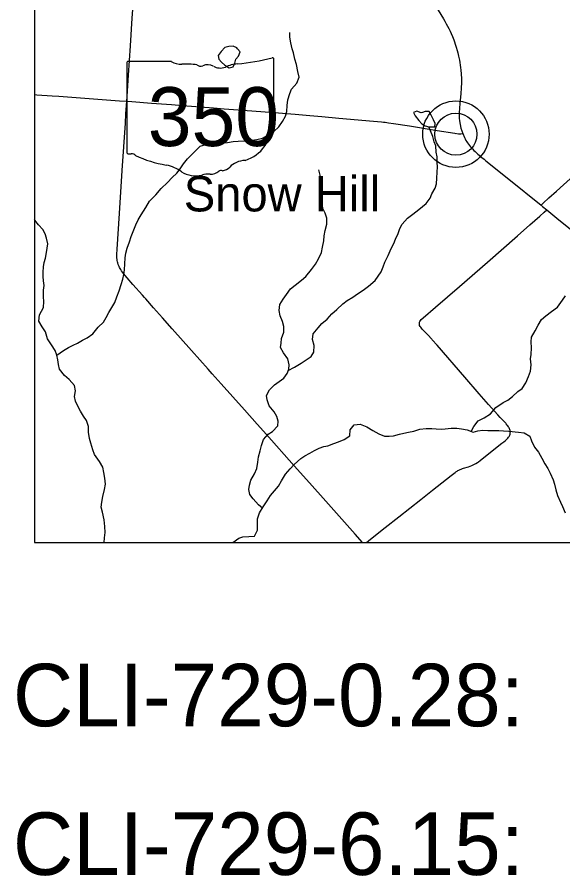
# Model space of a CAD drawing. Extents: x 0 to 34, y 0 to 22.
# Drawn here: x 24.749 to 25.971, y 13.559 to 15.483 of the extents above; entities that cross this region are included whole.
import ezdxf

# ---------------------------------------------------------------- set-up
doc = ezdxf.new("R2010")
doc.units = 0
for name, color, linetype in [('GM_X_Corporation', 7, 'Continuous'), ('GM_X_Major_River', 7, 'Continuous'), ('GM_X_Minor_Lake', 7, 'Continuous'), ('GM_X_Minor_River', 7, 'Continuous'), ('GM_X_State_Location', 7, 'Continuous'), ('GM_X_State_Route', 7, 'Continuous'), ('GM_X_State_Shield', 7, 'Continuous'), ('GM_X_Township_Road', 7, 'Continuous'), ('GM_X_Unincorporated', 7, 'Continuous'), ('GM_X_Unincorporated_Location', 7, 'Continuous'), ('GM_X_Unincorporated_Text', 7, 'Continuous'), ('SH_Text', 7, 'Continuous')]:
    doc.layers.add(name, color=color, linetype=linetype)

msp = doc.modelspace()

# ---------------------------------------------------------------- linework, layer by layer
at = {"layer": 'GM_X_Corporation'}
for points in [[(31.5875, 16.2767), (31.5875, 21.1059), (24.7875, 21.1059), (24.7875, 14.3059), (28.9316, 14.3059), (29.0116, 14.3654), (30.2271, 15.2782), (30.4064, 15.4161), (30.5426, 15.5161)], [(24.7875, 21.0754), (24.7875, 14.3059), (28.9316, 14.3059), (29.0116, 14.3654), (30.2271, 15.2782), (30.4064, 15.4161), (30.2965, 15.5727), (29.7308, 16.376), (29.4482, 16.7745), (28.3618, 18.3058), (27.7955, 19.0474), (27.3085, 19.7612), (27.122, 19.8586), (26.9873, 19.9283), (26.0175, 20.4289), (25.0178, 20.9472)]]:
    msp.add_lwpolyline(points, close=True, dxfattribs=at)
at = {"layer": 'GM_X_Major_River'}
for points in [[(25.232, 14.3059), (25.2452, 14.3156), (25.2548, 14.3189), (25.268, 14.3194), (25.2806, 14.32), (25.2876, 14.3336), (25.2874, 14.3476), (25.2875, 14.3586), (25.2919, 14.3722), (25.3, 14.3858), (25.3089, 14.3993), (25.3167, 14.4114), (25.3251, 14.4215), (25.334, 14.432), (25.3414, 14.4437), (25.3499, 14.4587), (25.3603, 14.4708), (25.3695, 14.4805), (25.3841, 14.494), (25.3937, 14.4999), (25.4044, 14.5062), (25.4147, 14.5118), (25.4258, 14.5169), (25.4357, 14.5206), (25.4452, 14.5228), (25.4581, 14.5275), (25.4688, 14.5316), (25.4818, 14.5367), (25.494, 14.5449), (25.4949, 14.5582), (25.5038, 14.5698), (25.5175, 14.5708), (25.5322, 14.5653), (25.5457, 14.5571), (25.5589, 14.549), (25.5721, 14.5439), (25.5823, 14.5441), (25.5918, 14.5451), (25.6051, 14.5488), (25.6154, 14.5505), (25.6253, 14.5527), (25.6374, 14.5552), (25.6508, 14.5596), (25.6652, 14.5613), (25.6781, 14.5615), (25.6879, 14.5602), (25.6985, 14.5597), (25.708, 14.5607), (25.7213, 14.5621), (25.7338, 14.5619), (25.744, 14.5602), (25.7573, 14.5586), (25.7705, 14.5527), (25.7807, 14.5564), (25.7925, 14.5573), (25.8031, 14.5568), (25.8145, 14.5571), (25.8278, 14.5569), (25.8384, 14.5564), (25.8505, 14.5551)], [(25.8505, 14.5551), (25.8717, 14.5533), (25.8849, 14.5512), (25.8973, 14.5442), (25.9014, 14.5339), (25.908, 14.5198), (25.9166, 14.5083), (25.924, 14.4949), (25.931, 14.482), (25.9377, 14.472), (25.9432, 14.4613), (25.9495, 14.4464), (25.9524, 14.4369), (25.9556, 14.424), (25.9596, 14.411), (25.9659, 14.3965), (25.9703, 14.3866), (25.9765, 14.3721)]]:
    msp.add_lwpolyline(points, dxfattribs=at)
at = {"layer": 'GM_X_Minor_Lake'}
for points in [[(25.2427, 15.412), (25.2409, 15.4142), (25.2326, 15.4173), (25.2231, 15.4166), (25.214, 15.4144), (25.2056, 15.4058), (25.1994, 15.3967), (25.2005, 15.3884), (25.2065, 15.3818), (25.2144, 15.3753)], [(25.2144, 15.3753), (25.2238, 15.3692), (25.2326, 15.3714), (25.2368, 15.3797), (25.2384, 15.3884), (25.2445, 15.3955), (25.2484, 15.4046), (25.2427, 15.412)], [(25.6571, 15.2691), (25.6543, 15.2681), (25.6445, 15.2724), (25.6365, 15.269), (25.6406, 15.2614), (25.6488, 15.2515), (25.6556, 15.2438), (25.6632, 15.2392), (25.6715, 15.2372)], [(25.6715, 15.2372), (25.6844, 15.2371), (25.6856, 15.2447), (25.6819, 15.2527), (25.6767, 15.263), (25.6718, 15.2714), (25.6627, 15.2711), (25.6571, 15.2691)]]:
    msp.add_lwpolyline(points, dxfattribs=at)
at = {"layer": 'GM_X_Minor_River'}
for points in [[(24.8378, 14.7257), (24.853, 14.736), (24.8637, 14.7424), (24.874, 14.748), (24.8839, 14.7525), (24.8954, 14.7588), (24.9053, 14.7644), (24.9183, 14.7734), (24.9305, 14.7881), (24.942, 14.7997), (24.9486, 14.8099), (24.9544, 14.8209), (24.9613, 14.8322), (24.9678, 14.8432), (24.9725, 14.8564), (24.9772, 14.8693), (24.9819, 14.884), (24.9858, 14.8961), (24.9878, 14.9064), (24.9894, 14.917), (24.9903, 14.9299), (24.9911, 14.9432), (24.9924, 14.9538), (24.9951, 14.9651), (25.0006, 14.9795), (25.0041, 14.9912), (25.0084, 15.0026), (25.015, 15.0177), (25.02, 15.029), (25.0265, 15.0396), (25.0373, 15.0562), (25.0454, 15.0706), (25.0592, 15.0849), (25.0715, 15.0988), (25.0856, 15.112), (25.096, 15.1236), (25.1063, 15.1334), (25.1144, 15.1432), (25.1213, 15.1538), (25.1305, 15.1654), (25.1447, 15.1794), (25.1585, 15.1933), (25.1741, 15.1981), (25.1847, 15.1983), (25.1984, 15.2001), (25.2101, 15.2012), (25.2204, 15.2022), (25.2326, 15.204), (25.2439, 15.2046), (25.2587, 15.2053), (25.2701, 15.2067), (25.2857, 15.2084), (25.2983, 15.2114), (25.3108, 15.2181), (25.3242, 15.2267), (25.3349, 15.2368), (25.3434, 15.2489), (25.3499, 15.261), (25.3527, 15.2712), (25.354, 15.2849), (25.3556, 15.2974), (25.3595, 15.3114), (25.3638, 15.3216), (25.3757, 15.3348), (25.3803, 15.348), (25.3778, 15.3606), (25.3749, 15.3765), (25.3712, 15.3887), (25.3683, 15.4024), (25.3646, 15.4119), (25.3617, 15.4252), (25.3595, 15.4378), (25.36, 15.4484)], [(25.3563, 14.6913), (25.3702, 14.6983), (25.3851, 14.7073), (25.3966, 14.7148), (25.4073, 14.7223), (25.4138, 14.7321), (25.4143, 14.7469), (25.4106, 14.7606), (25.4123, 14.7735), (25.423, 14.787), (25.4318, 14.7968), (25.4433, 14.8058), (25.4541, 14.8183), (25.4651, 14.828), (25.4785, 14.8408), (25.4885, 14.8476), (25.5007, 14.8558), (25.5114, 14.8629), (25.5243, 14.8711), (25.5358, 14.8798), (25.5507, 14.8925), (25.5576, 14.9023), (25.5642, 14.9121), (25.5685, 14.9235), (25.5723, 14.9337), (25.5804, 14.9484), (25.5867, 14.9643), (25.5925, 14.9753), (25.5963, 14.9855), (25.6025, 14.9983), (25.6064, 15.0089), (25.6111, 15.0188), (25.6237, 15.0327), (25.6352, 15.0417), (25.6485, 15.0518), (25.6654, 15.0653), (25.6742, 15.077), (25.6781, 15.0868), (25.685, 15.0993), (25.6882, 15.1091), (25.689, 15.122), (25.6895, 15.1357), (25.6904, 15.1475), (25.6901, 15.1569), (25.6895, 15.1699), (25.6877, 15.1805), (25.6867, 15.1942), (25.6833, 15.2037), (25.6804, 15.2155), (25.6715, 15.2372)], [(25.2983, 14.383), (25.2897, 14.3905), (25.2773, 14.4039), (25.2698, 14.4134), (25.2676, 14.4245), (25.2692, 14.4343), (25.2727, 14.4453), (25.2804, 14.4596), (25.2855, 14.4714), (25.2879, 14.4861), (25.2899, 14.4975), (25.2934, 14.5115), (25.2966, 14.5233), (25.3005, 14.5369), (25.3112, 14.5489), (25.3207, 14.5545), (25.3326, 14.5673), (25.3339, 14.578), (25.3305, 14.5879), (25.3249, 14.5985), (25.3137, 14.6119), (25.3089, 14.6252), (25.3074, 14.6355), (25.314, 14.6476), (25.3251, 14.6593), (25.3358, 14.6664), (25.3461, 14.6743), (25.3538, 14.6844), (25.3573, 14.6943), (25.3582, 14.7041), (25.3552, 14.7171), (25.3459, 14.7308), (25.3388, 14.7426), (25.34, 14.7525), (25.3412, 14.7627), (25.3463, 14.7767), (25.346, 14.79), (25.3431, 14.801), (25.3383, 14.8136), (25.3361, 14.8254), (25.3377, 14.8387), (25.3451, 14.8511), (25.352, 14.8613), (25.3612, 14.8741), (25.3715, 14.882), (25.3861, 14.8933), (25.3956, 14.9019), (25.4083, 14.9174), (25.4175, 14.9294), (25.4241, 14.9411), (25.4306, 14.9555), (25.433, 14.9672), (25.4358, 14.9816), (25.437, 14.9926), (25.4391, 15.0048), (25.4426, 15.0191), (25.4427, 15.0324), (25.4386, 15.0435), (25.4338, 15.0538), (25.432, 15.0671), (25.4322, 15.0811), (25.433, 15.0929), (25.4327, 15.1027), (25.431, 15.1157), (25.4277, 15.1286), (25.4247, 15.1404)], [(24.9434, 14.3059), (24.9448, 14.3162), (24.9457, 14.3287), (24.9454, 14.342), (24.9437, 14.3568), (24.94, 14.3739), (24.9371, 14.385), (24.9384, 14.3963), (24.9404, 14.4092), (24.9443, 14.4247), (24.9467, 14.4365), (24.9449, 14.4502), (24.9427, 14.4627), (24.9406, 14.4745), (24.9335, 14.4875), (24.9222, 14.5031), (24.9182, 14.5134), (24.9137, 14.5283), (24.9112, 14.5389), (24.9083, 14.5534), (24.9084, 14.5655), (24.9043, 14.5792), (24.8976, 14.5891), (24.8909, 14.6002), (24.8853, 14.6097), (24.8797, 14.6227), (24.8775, 14.633), (24.8792, 14.6455), (24.877, 14.6576), (24.8653, 14.6714), (24.8552, 14.6798), (24.8439, 14.694), (24.8417, 14.7046), (24.8403, 14.7149), (24.8378, 14.7259), (24.8341, 14.7362), (24.8255, 14.7488), (24.8168, 14.7622), (24.8121, 14.7778), (24.8046, 14.7888), (24.7975, 14.8014), (24.7991, 14.8155), (24.808, 14.8325), (24.8089, 14.8454), (24.8078, 14.856), (24.808, 14.8712), (24.8092, 14.8814), (24.8078, 14.8917), (24.8071, 14.9019), (24.8072, 14.9118), (24.8081, 14.9236), (24.8093, 14.933), (24.812, 14.9429), (24.8144, 14.9558), (24.8164, 14.9652), (24.8173, 14.9751), (24.8143, 14.9876), (24.8118, 14.9975), (24.8066, 15.0071), (24.7964, 15.0178), (24.7885, 15.0277), (24.7875, 15.0294)], [(25.7659, 14.5547), (25.772, 14.5656), (25.782, 14.5788), (25.7949, 14.5855), (25.8094, 14.5938), (25.821, 14.6081), (25.8378, 14.6197), (25.848, 14.6245), (25.8587, 14.6328), (25.8702, 14.6445), (25.8805, 14.6508), (25.8882, 14.6633), (25.8944, 14.6776), (25.8987, 14.6897), (25.9007, 14.7041), (25.8993, 14.7171), (25.9002, 14.7273), (25.9011, 14.7421), (25.9001, 14.7554), (25.9013, 14.7656), (25.9094, 14.7804), (25.9163, 14.7924), (25.9237, 14.8053), (25.9332, 14.8135), (25.9458, 14.8233), (25.9592, 14.833), (25.9704, 14.8485), (25.9773, 14.8583)]]:
    msp.add_lwpolyline(points, dxfattribs=at)
at = {"layer": 'GM_X_State_Route'}
for points in [[(25.6705, 15.5342), (25.7039, 15.4789), (25.7067, 15.4739), (25.7101, 15.468), (25.7131, 15.4621), (25.7158, 15.457), (25.7186, 15.4512), (25.7213, 15.4458), (25.724, 15.4395), (25.727, 15.4319), (25.7286, 15.427), (25.7303, 15.4219), (25.7323, 15.4151), (25.7343, 15.4081), (25.7358, 15.4025), (25.7376, 15.3954), (25.7396, 15.3863), (25.7404, 15.3812), (25.7414, 15.3752), (25.7421, 15.37), (25.743, 15.3635), (25.7437, 15.3554), (25.7442, 15.3448), (25.7443, 15.3355), (25.7437, 15.3242), (25.7426, 15.3112), (25.7408, 15.2889), (25.7393, 15.2685), (25.7391, 15.2617), (25.7393, 15.2562), (25.7398, 15.2501), (25.741, 15.2425), (25.7429, 15.2343), (25.7471, 15.222)], [(24.7875, 15.3092), (24.7929, 15.3088), (24.827, 15.3064), (24.8425, 15.3054), (24.8716, 15.3033), (24.9007, 15.3008), (24.9782, 15.2954), (24.9944, 15.2942), (25.0055, 15.2934), (25.0501, 15.2902), (25.0947, 15.2869), (25.1195, 15.2851), (25.1888, 15.2794), (25.2123, 15.2774), (25.2743, 15.2725), (25.3245, 15.2689), (25.3715, 15.2652), (25.4048, 15.2623), (25.4222, 15.2608), (25.4314, 15.26), (25.4692, 15.2566), (25.5131, 15.2524), (25.5385, 15.2502), (25.5652, 15.2478), (25.5694, 15.2474), (25.5732, 15.2471), (25.5774, 15.2466), (25.5809, 15.2461), (25.5921, 15.2445), (25.6276, 15.2389), (25.6895, 15.2287), (25.7294, 15.2226), (25.7377, 15.2214), (25.7407, 15.2212), (25.7429, 15.2214), (25.7471, 15.222)], [(25.7471, 15.222), (25.7508, 15.2128), (25.7523, 15.2098), (25.7542, 15.2065), (25.7561, 15.2034), (25.7576, 15.2011), (25.76, 15.1978), (25.7623, 15.1948), (25.7642, 15.1925), (25.7664, 15.1901), (25.7687, 15.1875), (25.7719, 15.1843), (25.7749, 15.1815), (25.7781, 15.1786), (25.7811, 15.1759), (25.7841, 15.1732), (25.7902, 15.1682), (25.795, 15.1642), (25.7989, 15.1609), (25.8502, 15.1196), (25.9225, 15.0612)], [(25.9225, 15.0612), (25.9275, 15.0659), (25.9402, 15.0777), (25.9573, 15.0931), (26.0348, 15.163)], [(25.9225, 15.0612), (25.9256, 15.0588), (25.9356, 15.0507)], [(25.9356, 15.0507), (25.958, 15.0326), (26.0115, 14.9892), (26.0644, 14.9468), (26.1136, 14.9069), (26.1325, 14.8917), (26.1686, 14.8623), (26.1818, 14.8519), (26.22, 14.821), (26.2442, 14.8015), (26.2521, 14.795), (26.258, 14.7903), (26.2636, 14.7856), (26.2698, 14.7802), (26.2798, 14.7717)]]:
    msp.add_lwpolyline(points, dxfattribs=at)
at = {"layer": 'GM_X_State_Shield'}
for p, q in [((25.3241, 15.2836), (25.3241, 15.3883)), ((24.9945, 15.3799), (24.9945, 15.1798)), ((25.0943, 15.3834), (24.9977, 15.3834)), ((25.324, 15.2837), (25.3241, 15.2836))]:
    msp.add_line(p, q, dxfattribs=at)
for centre, major_axis, start_param, end_param in [((25.2067, 15.6562), (0.3495, 0), 4.814394, 5.042369), ((25.3204, 15.3888), (0.00367, 0), 6.141152, 7.989035), ((24.9983, 15.3804), (0.00382, 0), 1.712693, 3.28349), ((25.1172, 15.4066), (0.037, 0), 4.042523, 4.731795), ((25.1295, 15.271), (0.133, 0), 1.404758, 1.657858), ((25.1597, 15.3814), (0.0107, 0), 3.836095, 5.185415), ((25.1754, 15.3583), (0.0222, 0), 0.950623, 2.079405), ((25.2041, 15.39), (0.0267, 0), 4.081561, 5.145723), ((25.2513, 15.3223), (0.0703, 0), 1.699011, 2.107814), ((25.3232, 15.276), (0.00568, 0), 1.883978, 3.671073), ((25.2871, 15.2627), (0.0341, 0), 5.934695, 6.695948), ((25.3202, 15.2832), (0.00393, 0), 5.05454, 6.418171), ((25.3372, 15.2398), (0.0248, 0), 2.387724, 3.262537), ((25.2263, 15.2265), (0.0874, 0), 5.101752, 6.440018), ((24.9983, 15.1794), (0.00385, 0), 3.00124, 4.508301), ((24.9989, 15.1998), (0.0294, 0), 4.665946, 4.897461), ((25.0049, 15.1683), (0.0106, 0), 0.519207, 1.627899), ((25.1387, 15.3481), (0.2524, 0), 4.195997, 4.488961), ((25.2631, 15.1236), (0.0479, 0), 1.647645, 2.488434), ((25.0635, 15.0899), (0.079, 0), 0.823519, 1.323587), ((25.1489, 15.1673), (0.0501, 0), 4.026481, 4.996735), ((25.1815, 15.1523), (0.0267, 0), 4.691044, 5.507374), ((25.2057, 15.1329), (0.00752, 0), 1.147584, 2.315152), ((25.2025, 15.1604), (0.0282, 0), 4.937069, 5.64225), ((25.1778, 15.0981), (0.0412, 0), 1.495662, 1.94098)]:
    msp.add_ellipse(centre, major_axis=major_axis, ratio=0.8, start_param=start_param, end_param=end_param, dxfattribs=at)
at = {"layer": 'GM_X_Township_Road'}
for points in [[(24.9944, 15.2942), (24.9951, 15.3048), (24.998, 15.3526), (25.0026, 15.4182), (25.0067, 15.4802), (25.0097, 15.5198)], [(25.5229, 14.3059), (25.5062, 14.3243), (25.488, 14.3447), (25.4703, 14.3647), (25.4403, 14.3987), (25.4039, 14.4395), (25.3696, 14.478), (25.3072, 14.548), (25.2869, 14.5707), (25.2585, 14.6028), (25.2062, 14.6611), (25.186, 14.6839), (25.1765, 14.6945), (25.1391, 14.7361), (25.0962, 14.7844), (25.0741, 14.8088), (25.0545, 14.8313), (25.0368, 14.8517), (25.0341, 14.8548), (25.0293, 14.8601), (25.008, 14.8839), (24.9954, 14.8985), (24.987, 14.9085), (24.9848, 14.9116), (24.9827, 14.9145), (24.981, 14.9172), (24.9797, 14.9193), (24.9783, 14.9219), (24.9771, 14.9243), (24.9754, 14.9283), (24.9741, 14.9324), (24.9735, 14.9347), (24.9729, 14.9372), (24.9726, 14.9401), (24.9722, 14.9434), (24.9722, 14.9479), (24.9722, 14.9508), (24.973, 14.9626), (24.9783, 15.0432), (24.9844, 15.1393), (24.9879, 15.192), (24.9913, 15.2453), (24.9926, 15.2664), (24.9944, 15.2942)], [(25.5314, 14.3059), (25.5366, 14.3101), (25.5736, 14.3395), (25.6043, 14.3638), (25.653, 14.4024), (25.6794, 14.4231), (25.7002, 14.4398), (25.7213, 14.4562), (25.7302, 14.463), (25.7319, 14.4641), (25.7343, 14.4658), (25.7364, 14.4669), (25.7386, 14.4682), (25.7411, 14.4693), (25.7437, 14.4705), (25.7463, 14.4715), (25.7489, 14.4725), (25.7603, 14.4757), (25.7636, 14.4769), (25.7673, 14.4782), (25.7703, 14.4796), (25.7735, 14.4811), (25.7762, 14.4828), (25.7799, 14.485), (25.7824, 14.4869), (25.7858, 14.4894), (25.8095, 14.5086), (25.8349, 14.5285), (25.8389, 14.5316), (25.8419, 14.5339), (25.8452, 14.5367), (25.8468, 14.5383), (25.8483, 14.5397), (25.8496, 14.5416), (25.8509, 14.5433), (25.8518, 14.5448), (25.8525, 14.5466), (25.8531, 14.5483), (25.8536, 14.5507), (25.8537, 14.5522), (25.8538, 14.5538), (25.8536, 14.5557), (25.8534, 14.5568), (25.8528, 14.5592), (25.8521, 14.5608), (25.8513, 14.5626), (25.8505, 14.5638), (25.8497, 14.5652), (25.8483, 14.5671), (25.847, 14.5688), (25.8447, 14.5714), (25.8433, 14.5729), (25.8309, 14.5861), (25.8255, 14.5921), (25.8048, 14.6152), (25.7838, 14.639), (25.7515, 14.6759), (25.6895, 14.7479), (25.6788, 14.7601), (25.6776, 14.7615), (25.6692, 14.7707), (25.6563, 14.7841), (25.653, 14.7879), (25.6516, 14.7899), (25.6506, 14.7922), (25.6502, 14.794), (25.65, 14.7958), (25.6501, 14.7977), (25.6505, 14.7995), (25.6512, 14.8012), (25.6525, 14.8033), (25.6541, 14.8052), (25.6582, 14.809), (25.6861, 14.8329), (25.7395, 14.8795), (25.8023, 14.9341), (25.8697, 14.993), (25.8973, 15.0171), (25.9195, 15.037), (25.9299, 15.0458), (25.9356, 15.0507)]]:
    msp.add_lwpolyline(points, dxfattribs=at)
at = {"layer": 'GM_X_Unincorporated'}
for radius in [0.0744, 0.0472]:
    msp.add_circle((25.7318, 15.2205), radius, dxfattribs=at)
at = {"layer": 'GM_X_Unincorporated_Location'}
msp.add_line((25.7318, 15.2205), (25.7318, 15.2205), dxfattribs=at)

# ---------------------------------------------------------------- texts
at = {"layer": 'GM_X_State_Location'}
msp.add_text('350', height=0.000189, rotation=0, dxfattribs=at).set_placement((25.0887, 15.2528))
for s in ['s', 'r']:
    msp.add_text(s, height=0.000189, dxfattribs=at).set_placement((25.1556, 15.2666))
at = {"layer": 'GM_X_State_Shield'}
msp.add_text('350', height=0.13184, dxfattribs=at).set_placement((25.0414, 15.1939))
at = {"layer": 'GM_X_Unincorporated_Text'}
msp.add_text('Snow Hill', height=0.07898, rotation=0, dxfattribs=at).set_placement((25.1221, 15.0475))
at = {"layer": 'SH_Text'}
for s, p in [('CLI-729-0.28:', (24.7393, 13.8943)), ('CLI-729-6.15:', (24.7393, 13.5613))]:
    msp.add_text(s, height=0.14, dxfattribs=at).set_placement(p)

doc.saveas('drawing.dxf')
